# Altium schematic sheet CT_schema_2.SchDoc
size 276 x 169 mm
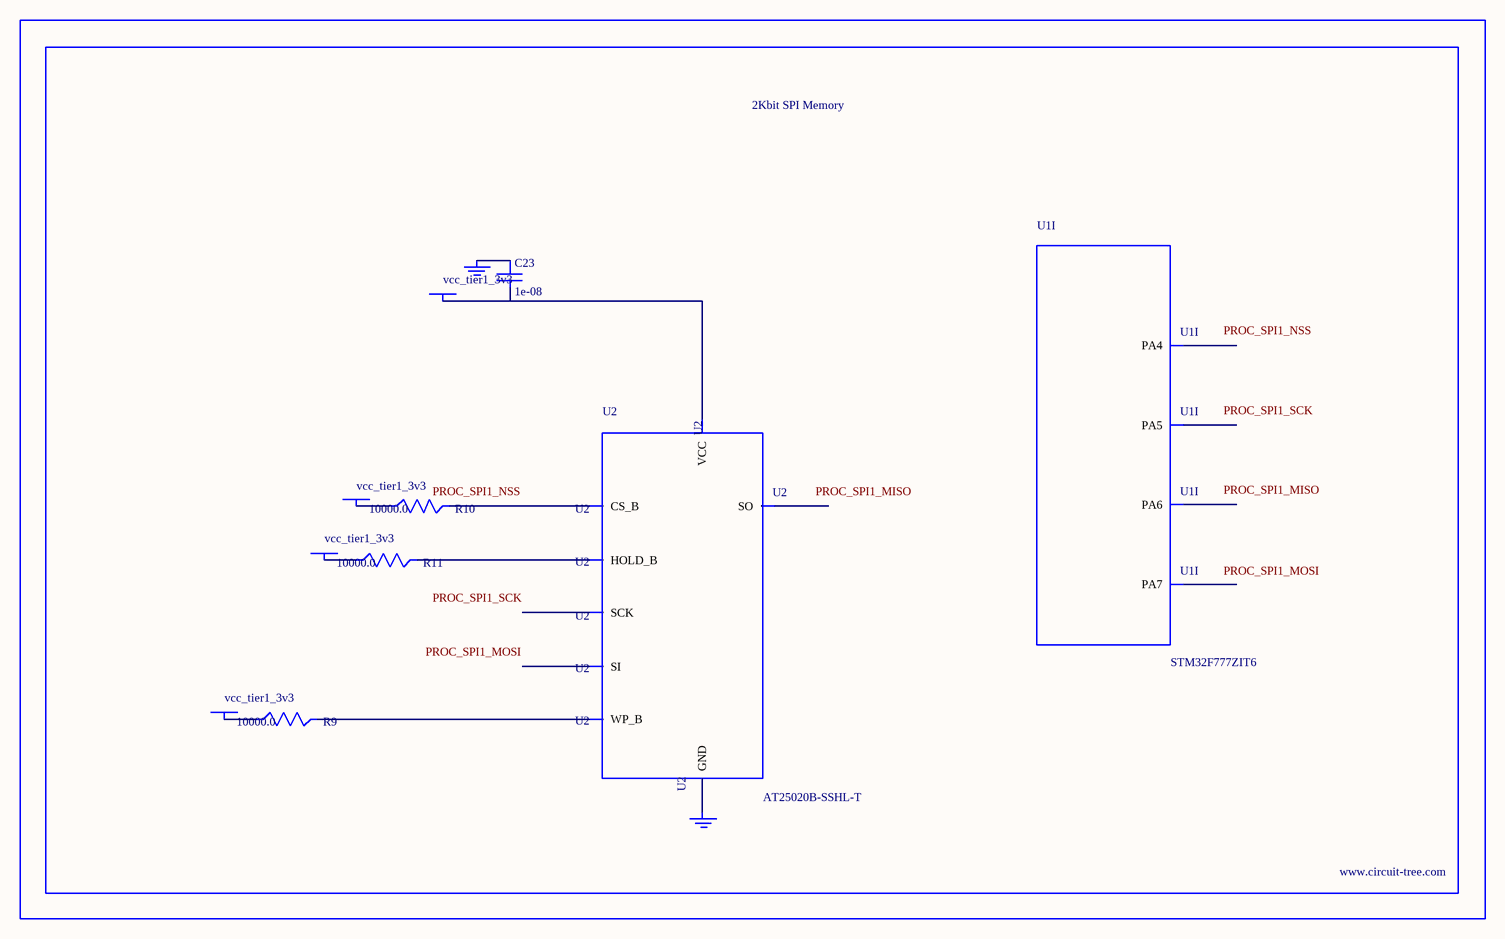
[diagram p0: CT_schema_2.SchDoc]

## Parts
BORDER1  (no value)
C23  1e-08  [C0402]
GND_INSTANCE_1_0  (no value)
GND_INSTANCE_1_1  (no value)
POWER_INSTANCE_1_0  vcc_tier1_3v3
POWER_INSTANCE_1_1  vcc_tier1_3v3
POWER_INSTANCE_1_2  vcc_tier1_3v3
POWER_INSTANCE_1_3  vcc_tier1_3v3
R9  10000.0  [R0603]
R10  10000.0  [R0603]
R11  10000.0  [R0603]
U1  STM32F777ZIT6  [LQFP144]  (part I of 13)
U2  AT25020B-SSHL-T  [SOIC-8]

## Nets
NetC23_1: C23.1 GND_INSTANCE_1_0.0(GND)
NetC23_2: C23.2 POWER_INSTANCE_1_3.0(PWR) U2.8(VCC)
NetGND_INSTANCE_1_1_0: GND_INSTANCE_1_1.0(GND) U2.4(GND)
NetPOWER_INSTANCE_1_0_0: POWER_INSTANCE_1_0.0(PWR) R10.1
NetPOWER_INSTANCE_1_1_0: POWER_INSTANCE_1_1.0(PWR) R9.1
NetPOWER_INSTANCE_1_2_0: POWER_INSTANCE_1_2.0(PWR) R11.1
NetR9_2: R9.2 U2.3(WP_B)
NetR10_2: R10.2 U2.1(CS_B)
NetR11_2: R11.2 U2.7(HOLD_B)

Not connected (* = marked no-connect by the designer): U1 40(PA4) 41(PA5) 42(PA6) 43(PA7); U2 2(SO) 5(SI) 6(SCK)

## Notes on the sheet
- Labels drawn without touching a wire or pin: PROC_SPI1_MISO, PROC_SPI1_MOSI, PROC_SPI1_NSS, PROC_SPI1_SCK

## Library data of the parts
BORDER1 = BORDER_PAGE1
C23 = C0402C103K3RAC
GND_INSTANCE_1_0 GND_INSTANCE_1_1 = GND
POWER_INSTANCE_1_0-POWER_INSTANCE_1_3 = PWR
R9-R11 = RC0603JR-0710KL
